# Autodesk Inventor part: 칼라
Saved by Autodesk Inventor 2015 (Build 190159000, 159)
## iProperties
Created: 2026-07
Part Number: 칼라
Material: 일반
Document SubType Name: Modeling
Designer: USER
Density: 1 g/cm^3
Appearance: 기본값
Author: USER
Author: jhkim
Creation Date: 2026-07-01
Sending System: Autodesk Inventor 2027
Preprocessor: ST-DEVELOPER v20.1
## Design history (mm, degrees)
node "칼라1"
node "솔리드1"
node "기준1"
